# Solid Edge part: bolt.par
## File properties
Author: Deepak Maini
Template: Normal.par
Last saved by: CADCIM
Revision: 4
Application: Solid Edge
Accuracy: 0.99
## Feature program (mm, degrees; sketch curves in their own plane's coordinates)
sketch for "unnamed RevolvedProtrusion 1" plane through (0, 0, 0) normal (0, -1, 0) x-axis (1, 0, 0)
  line (0, 40.7664) -> (14.7729, 40.7664)
  line (14.7729, 40.7664) -> (14.7729, 29.2752)
  line (14.7729, 29.2752) -> (8.0228, 29.2752)
  line (8.0228, 29.2752) -> (8.0228, -6.0192)
  line (8.0228, -6.0192) -> (0, -6.0192)
  line (0, -6.0192) -> (0, 40.7664)
revolve "unnamed RevolvedProtrusion 1" add full turn 360 deg
sketch for "unnamed Cutout 1" plane through (0, 0, 40.7664) normal (0, 0, 1) x-axis (1, 0, 0)
  line (-7.0309, 0) -> (-3.9268, 6.0697)
  line (-3.9268, 6.0697) -> (3.076, 6.0697)
  line (3.076, 6.0697) -> (7.0309, 0)
  line (7.0309, 0) -> (3.2724, -6.223)
  line (3.2724, -6.223) -> (-3.2724, -6.223)
  line (-3.2724, -6.223) -> (-7.0309, 0)
extrude "unnamed Cutout 1" cut finite 6.35 along -normal
chamfer "Chamfer_1" setback 2
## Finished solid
Body 1: solid body, 13 faces, 23 edges, 12 vertices.
  Faces by surface: plane 10, cylinder 2, cone 1
  Edges by curve: line 18, circle 5
Bounding box of the edges (mm): 29.546 x 29.546 x 46.786, from (-14.7729, -14.7729, -6.0192) to (14.7729, 14.7729, 40.7664).
Cylindrical faces by radius (mm): R8.0228 x1, R14.7729 x1
Conical faces (half-angle, radius in mm at the cone's reference point): 45 deg R12.7729 x1
Planar faces by outward normal: +y 1, +z 2, -y 1, -z 2, oblique 4
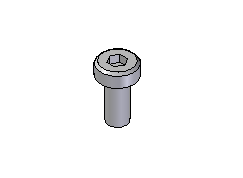
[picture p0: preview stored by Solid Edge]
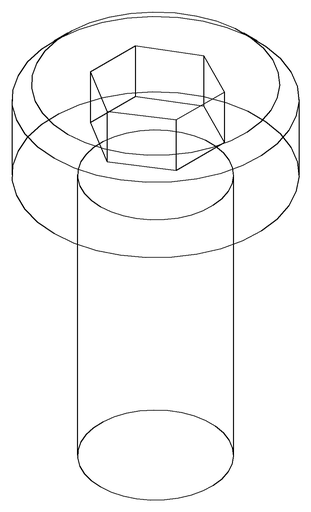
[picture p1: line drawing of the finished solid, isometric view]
